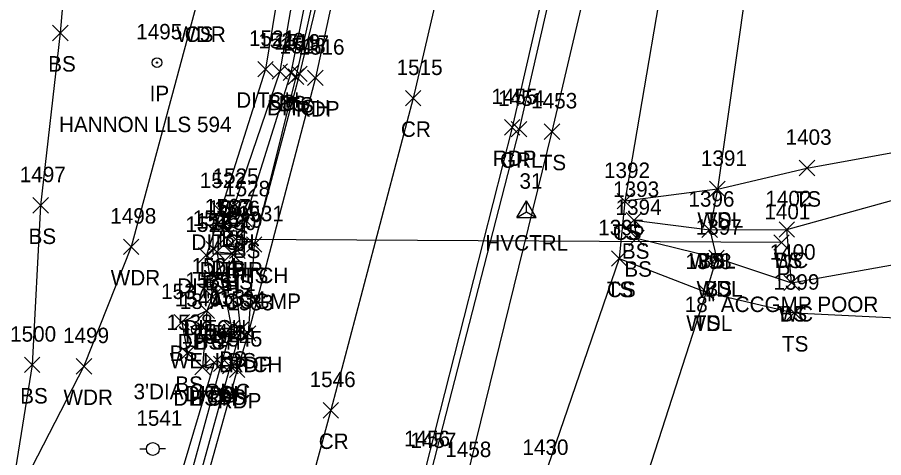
# Model space of a CAD drawing. Extents: x 1551995 to 1555700, y 777276 to 783130.
# Drawn here: x 1554796.1 to 1554908, y 777646.9 to 777703.8 of the extents above; entities that cross this region are included whole.
import ezdxf

# ---------------------------------------------------------------- set-up
doc = ezdxf.new("R2010")
doc.units = 0
for name, color, linetype in [('C_A', 7, 'Continuous'), ('C_I', 7, 'Continuous'), ('CPSM', 7, 'Continuous'), ('D_A', 7, 'Continuous'), ('D_C', 7, 'Continuous'), ('D_I', 7, 'Continuous'), ('D_TIC', 7, 'Continuous'), ('DCP', 7, 'Continuous'), ('DD', 7, 'Continuous'), ('DS', 7, 'Continuous'), ('L_A', 7, 'Continuous'), ('L_I', 7, 'Continuous'), ('L_TIC', 7, 'Continuous'), ('LAWA', 7, 'Continuous'), ('LAWE', 7, 'Continuous'), ('LELB', 7, 'Continuous'), ('M_A', 7, 'Continuous'), ('M_C', 7, 'Continuous'), ('M_I', 7, 'Continuous'), ('MPIR', 7, 'Continuous'), ('P_A', 7, 'Continuous'), ('P_I', 7, 'Continuous'), ('P_TIC', 7, 'Continuous'), ('PET', 7, 'Continuous'), ('PRC', 7, 'Continuous'), ('R_A', 7, 'Continuous'), ('R_I', 7, 'Continuous'), ('R_TIC', 7, 'Continuous'), ('RGR', 7, 'Continuous'), ('U_A', 7, 'Continuous'), ('U_C', 7, 'Continuous'), ('U_I', 7, 'Continuous'), ('UP', 7, 'Continuous'), ('UWW', 7, 'Continuous')]:
    doc.layers.add(name, color=color, linetype=linetype)

msp = doc.modelspace()

# ---------------------------------------------------------------- linework, layer by layer
at = {"layer": 'CPSM'}
for p, q in [((1554860.61, 777677.95), (1554861.86, 777680.12)), ((1554863.11, 777677.95), (1554861.86, 777680.12)), ((1554861.86, 777678.67), (1554861.86, 777680.12)), ((1554860.61, 777677.95), (1554861.86, 777678.67)), ((1554861.86, 777678.67), (1554861.86, 777678.67)), ((1554861.86, 777678.67), (1554863.11, 777677.95)), ((1554860.61, 777677.95), (1554863.11, 777677.95))]:
    msp.add_line(p, q, dxfattribs=at)
at = {"layer": 'D_TIC'}
for points in [[(1554827.13, 777696.14), (1554829.13, 777698.14)], [(1554829.13, 777696.14), (1554827.13, 777698.14)], [(1554831.08, 777695.16), (1554833.08, 777697.16)], [(1554833.08, 777695.16), (1554831.08, 777697.16)], [(1554821.33, 777677.76), (1554823.33, 777679.76)], [(1554823.33, 777677.76), (1554821.33, 777679.76)], [(1554822.04, 777674.36), (1554824.04, 777676.36)], [(1554824.04, 777674.36), (1554822.04, 777676.36)], [(1554823.28, 777674.12), (1554825.28, 777676.12)], [(1554825.28, 777674.12), (1554823.28, 777676.12)], [(1554825.68, 777673.46), (1554827.68, 777675.46)], [(1554827.68, 777673.46), (1554825.68, 777675.46)], [(1554893.81, 777673.72), (1554895.81, 777675.72)], [(1554895.81, 777673.72), (1554893.81, 777675.72)], [(1554819.5, 777672.08), (1554821.5, 777674.08)], [(1554821.5, 777672.08), (1554819.5, 777674.08)], [(1554820.28, 777666.69), (1554822.28, 777668.69)], [(1554822.28, 777666.69), (1554820.28, 777668.69)], [(1554819.54, 777664.87), (1554821.54, 777666.87)], [(1554821.54, 777664.87), (1554819.54, 777666.87)], [(1554824.9, 777661.94), (1554826.9, 777663.94)], [(1554826.9, 777661.94), (1554824.9, 777663.94)], [(1554818.99, 777657.61), (1554820.99, 777659.61)], [(1554820.99, 777657.61), (1554818.99, 777659.61)], [(1554820.52, 777658.17), (1554822.52, 777660.17)], [(1554822.52, 777658.17), (1554820.52, 777660.17)]]:
    msp.add_lwpolyline(points, dxfattribs=at)
at = {"layer": 'DCP'}
msp.add_lwpolyline([(1554894.81, 777674.72), (1554824.28, 777675.12)], dxfattribs=at)
at = {"layer": 'DD'}
for points in [[(1554922.06, 778109.96), (1554923.19, 778109.15), (1554925.69, 778108.05), (1554928.67, 778106.77), (1554922.03, 778089.94), (1554922.01, 778087.44), (1554918.96, 778075.67), (1554907.32, 778037.79), (1554897.01, 777996.11), (1554888.71, 777961.75), (1554879.52, 777917.82), (1554870.92, 777875.83), (1554859.53, 777827.03), (1554848.28, 777775.3), (1554842.42, 777742.65), (1554832.08, 777696.16), (1554826.68, 777674.46), (1554825.9, 777662.94)], [(1554853.39, 777826.98), (1554841.81, 777777.5), (1554835.76, 777743.69), (1554828.13, 777697.14), (1554822.33, 777678.76), (1554820.5, 777673.08), (1554821.28, 777667.69), (1554820.54, 777665.87), (1554819.99, 777658.61), (1554821.52, 777659.17), (1554812.27, 777628.19), (1554798.58, 777600.46), (1554777.91, 777552.75), (1554765.73, 777525.09), (1554749.72, 777489.17), (1554733.83, 777456.87), (1554735, 777456.04), (1554736.9, 777455.11), (1554739.85, 777453.59)]]:
    msp.add_lwpolyline(points, dxfattribs=at)
at = {"layer": 'DS'}
for p, q in [((1554821.38, 777677.21), (1554825.38, 777677.21)), ((1554821.38, 777673.21), (1554821.39, 777677.21)), ((1554822.38, 777676.21), (1554824.38, 777676.21)), ((1554822.38, 777674.21), (1554822.38, 777676.21)), ((1554824.38, 777676.21), (1554824.38, 777674.21)), ((1554825.38, 777677.21), (1554825.38, 777673.21)), ((1554823.38, 777675.22), (1554823.38, 777675.22)), ((1554824.38, 777674.21), (1554822.38, 777674.21)), ((1554825.38, 777673.21), (1554821.38, 777673.21)), ((1554823.88, 777673.21), (1554824.38, 777673.21))]:
    msp.add_line(p, q, dxfattribs=at)
at = {"layer": 'L_TIC'}
for points in [[(1554800.62, 777700.82), (1554802.62, 777702.82)], [(1554802.62, 777700.82), (1554800.62, 777702.82)], [(1554828.99, 777695.83), (1554830.99, 777697.83)], [(1554830.99, 777695.83), (1554828.99, 777697.83)], [(1554830.41, 777695.67), (1554832.41, 777697.67)], [(1554832.41, 777695.67), (1554830.41, 777697.67)], [(1554831.54, 777695.52), (1554833.54, 777697.52)], [(1554833.54, 777695.52), (1554831.54, 777697.52)], [(1554864.16, 777688.06), (1554866.16, 777690.06)], [(1554866.16, 777688.06), (1554864.16, 777690.06)], [(1554897.11, 777683.35), (1554899.11, 777685.35)], [(1554899.11, 777683.35), (1554897.11, 777685.35)], [(1554885.53, 777680.63), (1554887.53, 777682.63)], [(1554887.53, 777680.63), (1554885.53, 777682.63)], [(1554885.53, 777680.63), (1554887.53, 777682.63)], [(1554887.53, 777680.63), (1554885.53, 777682.63)], [(1554885.53, 777680.63), (1554887.53, 777682.63)], [(1554887.53, 777680.63), (1554885.53, 777682.63)], [(1554873.58, 777679.06), (1554875.58, 777681.06)], [(1554875.58, 777679.06), (1554873.58, 777681.06)], [(1554873.58, 777679.06), (1554875.58, 777681.06)], [(1554875.58, 777679.06), (1554873.58, 777681.06)], [(1554798.08, 777678.52), (1554800.08, 777680.52)], [(1554800.08, 777678.52), (1554798.08, 777680.52)], [(1554822.99, 777678.3), (1554824.99, 777680.3)], [(1554824.99, 777678.3), (1554822.99, 777680.3)], [(1554824.48, 777676.69), (1554826.48, 777678.69)], [(1554826.48, 777676.69), (1554824.48, 777678.69)], [(1554874.75, 777676.61), (1554876.75, 777678.61)], [(1554876.75, 777676.61), (1554874.75, 777678.61)], [(1554874.75, 777676.61), (1554876.75, 777678.61)], [(1554876.75, 777676.61), (1554874.75, 777678.61)], [(1554884.54, 777675.35), (1554886.54, 777677.35)], [(1554886.54, 777675.35), (1554884.54, 777677.35)], [(1554884.54, 777675.35), (1554886.54, 777677.35)], [(1554886.54, 777675.35), (1554884.54, 777677.35)], [(1554894.5, 777675.41), (1554896.5, 777677.41)], [(1554896.5, 777675.41), (1554894.5, 777677.41)], [(1554894.5, 777675.41), (1554896.5, 777677.41)], [(1554896.5, 777675.41), (1554894.5, 777677.41)], [(1554875.07, 777674.29), (1554877.07, 777676.29)], [(1554877.07, 777674.29), (1554875.07, 777676.29)], [(1554809.77, 777673.16), (1554811.77, 777675.16)], [(1554811.77, 777673.16), (1554809.77, 777675.16)], [(1554825.68, 777673.46), (1554827.68, 777675.46)], [(1554827.68, 777673.46), (1554825.68, 777675.46)], [(1554820.48, 777672.86), (1554822.48, 777674.86)], [(1554822.48, 777672.86), (1554820.48, 777674.86)], [(1554820.86, 777672.52), (1554822.86, 777674.52)], [(1554822.86, 777672.52), (1554820.86, 777674.52)], [(1554820.86, 777672.52), (1554822.86, 777674.52)], [(1554822.86, 777672.52), (1554820.86, 777674.52)], [(1554822.78, 777672.32), (1554824.78, 777674.32)], [(1554824.78, 777672.32), (1554822.78, 777674.32)], [(1554822.78, 777672.32), (1554824.78, 777674.32)], [(1554824.78, 777672.32), (1554822.78, 777674.32)], [(1554823.51, 777672.63), (1554825.51, 777674.63)], [(1554825.51, 777672.63), (1554823.51, 777674.63)], [(1554872.83, 777671.65), (1554874.83, 777673.65)], [(1554874.83, 777671.65), (1554872.83, 777673.65)], [(1554872.83, 777671.65), (1554874.83, 777673.65)], [(1554874.83, 777671.65), (1554872.83, 777673.65)], [(1554885.43, 777671.72), (1554887.43, 777673.72)], [(1554887.43, 777671.72), (1554885.43, 777673.72)], [(1554885.43, 777671.72), (1554887.43, 777673.72)], [(1554887.43, 777671.72), (1554885.43, 777673.72)], [(1554895.13, 777668.49), (1554897.13, 777670.49)], [(1554897.13, 777668.49), (1554895.13, 777670.49)], [(1554895.13, 777668.49), (1554897.13, 777670.49)], [(1554897.13, 777668.49), (1554895.13, 777670.49)], [(1554895.13, 777668.49), (1554897.13, 777670.49)], [(1554897.13, 777668.49), (1554895.13, 777670.49)], [(1554884.1, 777667.28), (1554886.1, 777669.28)], [(1554886.1, 777667.28), (1554884.1, 777669.28)], [(1554884.1, 777667.28), (1554886.1, 777669.28)], [(1554886.1, 777667.28), (1554884.1, 777669.28)], [(1554819.54, 777664.87), (1554821.54, 777666.87)], [(1554821.54, 777664.87), (1554819.54, 777666.87)], [(1554895.47, 777664.61), (1554897.47, 777666.61)], [(1554897.47, 777664.61), (1554895.47, 777666.61)], [(1554816.33, 777663.4), (1554818.33, 777665.4)], [(1554818.33, 777663.4), (1554816.33, 777665.4)], [(1554822.73, 777662.64), (1554824.73, 777664.64)], [(1554824.73, 777662.64), (1554822.73, 777664.64)], [(1554823.92, 777662.42), (1554825.92, 777664.42)], [(1554825.92, 777662.42), (1554823.92, 777664.42)], [(1554817.04, 777659.4), (1554819.04, 777661.4)], [(1554819.04, 777659.4), (1554817.04, 777661.4)], [(1554797, 777657.89), (1554799, 777659.89)], [(1554799, 777657.89), (1554797, 777659.89)], [(1554803.68, 777657.7), (1554805.68, 777659.7)], [(1554805.68, 777657.7), (1554803.68, 777659.7)], [(1554818.99, 777657.61), (1554820.99, 777659.61)], [(1554820.99, 777657.61), (1554818.99, 777659.61)], [(1554821.4, 777658.03), (1554823.4, 777660.03)], [(1554823.4, 777658.03), (1554821.4, 777660.03)], [(1554822.59, 777657.72), (1554824.59, 777659.72)], [(1554824.59, 777657.72), (1554822.59, 777659.72)]]:
    msp.add_lwpolyline(points, dxfattribs=at)
at = {"layer": 'LAWA'}
for points in [[(1554924.17, 777845.95), (1554911.99, 777797.39), (1554901.73, 777752.36), (1554891.43, 777715.92), (1554886.53, 777681.63), (1554885.54, 777676.35), (1554886.43, 777672.72), (1554885.1, 777668.28), (1554876.24, 777640.92), (1554874.65, 777639.02), (1554865.05, 777604.93), (1554832.26, 777556.58), (1554828.6, 777545), (1554825.77, 777534.55), (1554825.26, 777531.03), (1554824.11, 777527.47), (1554817.13, 777514.36), (1554810.78, 777500.84), (1554797.7, 777469.38), (1554813.54, 777462.7)], [(1554848.67, 777827.4), (1554836.72, 777779.63), (1554829.79, 777744.11), (1554825.78, 777741.3), (1554822.18, 777720.94), (1554819.26, 777705.66), (1554810.77, 777674.16), (1554804.68, 777658.7), (1554794.95, 777639.81), (1554796.98, 777635.44), (1554794.4, 777626.38), (1554790.25, 777608.46), (1554781.8, 777582.48), (1554770.39, 777556.32), (1554759.95, 777527.2), (1554742.53, 777489.58), (1554728.19, 777462.54)]]:
    msp.add_lwpolyline(points, dxfattribs=at)
at = {"layer": 'LAWE'}
for points in [[(1554896.13, 777669.49), (1554914.18, 777672.74), (1554933.67, 777664.23), (1554957.57, 777659.67), (1554982.43, 777660.34), (1555001.98, 777663.11), (1555028.12, 777669.98), (1555046.42, 777677.46), (1555063.93, 777692.17), (1555074.78, 777708.2), (1555088.15, 777717.7), (1555098.22, 777729.19), (1555108.92, 777737.75), (1555125.5, 777739.97), (1555133.42, 777752.91), (1555147.36, 777756.73)], [(1554896.13, 777669.49), (1554895.5, 777676.41), (1554916.66, 777682.24), (1554936.86, 777671.45), (1554957.7, 777666.95), (1554983.51, 777668.08)]]:
    msp.add_lwpolyline(points, dxfattribs=at)
at = {"layer": 'LELB'}
for points in [[(1554956.78, 778082.85), (1554952.54, 778067.25), (1554941.7, 778025.45), (1554932.23, 777987.42), (1554924.92, 777953.42), (1554914.28, 777909.64), (1554906.04, 777867.54), (1554895.88, 777821.34), (1554882.23, 777767.05), (1554874.85, 777730.37), (1554865.16, 777689.06), (1554854.06, 777643.96), (1554841.07, 777598.56), (1554825.8, 777560.58)], [(1554954.84, 778026.93), (1554940.94, 777981.64), (1554932.87, 777954.14), (1554929.76, 777924.84), (1554918.75, 777893.91), (1554912.39, 777848.48), (1554900.26, 777799.7), (1554891.71, 777757.62), (1554881.43, 777720.27), (1554874.58, 777680.06), (1554873.83, 777672.65), (1554864.12, 777644.24), (1554854.56, 777607.14), (1554832.26, 777556.58)], [(1554818.74, 777989.99), (1554826.95, 777965.67), (1554828.21, 777938.79), (1554827.61, 777892.43), (1554825.56, 777859.47), (1554820.31, 777829.58), (1554817.04, 777800.55), (1554813.37, 777784.98), (1554810.59, 777751.68), (1554805.09, 777735), (1554803.57, 777724.87), (1554801.62, 777701.82), (1554799.08, 777679.52), (1554798, 777658.89), (1554794.95, 777639.81), (1554778.13, 777607.5), (1554759.36, 777559.57), (1554752.31, 777545.79)], [(1554870.92, 777875.83), (1554861.08, 777826.54), (1554850.05, 777774.56), (1554843.76, 777742.91), (1554832.54, 777696.52), (1554826.68, 777674.46)], [(1554855.73, 777827.33), (1554843.83, 777776.52), (1554838.11, 777743.68), (1554829.99, 777696.83), (1554823.99, 777679.3), (1554821.48, 777673.86), (1554821.86, 777673.52), (1554823.73, 777663.64), (1554822.4, 777659.03), (1554813.94, 777627.98), (1554800.18, 777599.92), (1554780.06, 777551.51), (1554767.45, 777524.55), (1554751.73, 777488.16), (1554735, 777456.04)], [(1554857.76, 777827.38), (1554846.36, 777775.83), (1554840.77, 777743.18), (1554831.41, 777696.67), (1554825.48, 777677.69), (1554824.51, 777673.63), (1554823.78, 777673.32), (1554824.92, 777663.42), (1554823.59, 777658.72), (1554814.97, 777627.54), (1554801.99, 777599.47), (1554782.65, 777550.32), (1554769.22, 777523.47), (1554754.18, 777487.46), (1554736.9, 777455.11)], [(1554886.53, 777681.63), (1554898.11, 777684.35), (1554919.59, 777688.24), (1554946.32, 777678.67), (1554960.8, 777672.01), (1554976.86, 777671.82)], [(1554886.53, 777681.63), (1554874.58, 777680.06)], [(1554875.75, 777677.61), (1554876.07, 777675.29), (1554886.43, 777672.72), (1554896.13, 777669.49)], [(1554875.75, 777677.61), (1554885.54, 777676.35), (1554895.5, 777676.41)], [(1554821.86, 777673.52), (1554823.78, 777673.32)], [(1554873.83, 777672.65), (1554885.1, 777668.28), (1554896.47, 777665.61), (1554911.4, 777664.89), (1554930.69, 777655.48), (1554958.85, 777648.16), (1554982.59, 777653.45), (1554998.31, 777654.1)], [(1554820.54, 777665.87), (1554817.33, 777664.4), (1554818.04, 777660.4), (1554819.99, 777658.61)]]:
    msp.add_lwpolyline(points, dxfattribs=at)
at = {"layer": 'MPIR'}
for radius in [0.625, 0.0833]:
    msp.add_circle((1554814.12, 777697.99), radius, dxfattribs=at)
at = {"layer": 'P_TIC'}
for points in [[(1554833.58, 777695.01), (1554835.58, 777697.01)], [(1554835.58, 777695.01), (1554833.58, 777697.01)], [(1554846.21, 777692.38), (1554848.21, 777694.38)], [(1554848.21, 777692.38), (1554846.21, 777694.38)], [(1554859.02, 777688.61), (1554861.02, 777690.61)], [(1554861.02, 777688.61), (1554859.02, 777690.61)], [(1554824.9, 777661.94), (1554826.9, 777663.94)], [(1554826.9, 777661.94), (1554824.9, 777663.94)], [(1554823.47, 777657.25), (1554825.47, 777659.25)], [(1554825.47, 777657.25), (1554823.47, 777659.25)], [(1554835.59, 777652.01), (1554837.59, 777654.01)], [(1554837.59, 777652.01), (1554835.59, 777654.01)]]:
    msp.add_lwpolyline(points, dxfattribs=at)
at = {"layer": 'PET'}
for points in [[(1554862.74, 777826.66), (1554851.19, 777774.32), (1554844.64, 777742.45), (1554834.58, 777696.01), (1554825.9, 777662.94), (1554824.47, 777658.25), (1554815.91, 777627.5), (1554805.87, 777597.98), (1554786.84, 777548.46), (1554774.55, 777520.74), (1554758.12, 777485.1), (1554742.1, 777452.42), (1554722.77, 777413.11), (1554709.98, 777388.33), (1554692.97, 777354.45), (1554662.63, 777294.3)], [(1554889.9, 777822.39), (1554877.4, 777767.74), (1554869.61, 777731.46), (1554860.02, 777689.61), (1554848.79, 777645.37), (1554834.77, 777600.99), (1554821.88, 777564.77), (1554812, 777537.71), (1554799.6, 777509.17), (1554784.62, 777476.27), (1554767.28, 777440.72), (1554755.97, 777417.1), (1554737.76, 777381.53), (1554717.46, 777342.52), (1554685.83, 777281.18)]]:
    msp.add_lwpolyline(points, dxfattribs=at)
at = {"layer": 'PRC'}
msp.add_lwpolyline([(1554876.72, 777824.26), (1554864.6, 777770.35), (1554858.03, 777739.92), (1554847.21, 777693.38), (1554836.59, 777653.01), (1554828.61, 777623.61), (1554818.04, 777593.07), (1554799.63, 777543.85), (1554787.19, 777515.25), (1554771.79, 777480.71), (1554754.78, 777446.13), (1554727.16, 777390.73), (1554704.95, 777347.63), (1554675, 777287.76)], dxfattribs=at)
at = {"layer": 'R_TIC'}
for points in [[(1554859.9, 777688.38), (1554861.9, 777690.38)], [(1554861.9, 777688.38), (1554859.9, 777690.38)]]:
    msp.add_lwpolyline(points, dxfattribs=at)
at = {"layer": 'RGR'}
msp.add_lwpolyline([(1555039.56, 778268.3), (1555013.62, 778223), (1554996.63, 778189.88), (1554979.88, 778154.08), (1554968.24, 778124.65), (1554958.2, 778096.32), (1554950.97, 778072.94), (1554937.27, 778027.95), (1554927.65, 777988.1), (1554919.66, 777954.37), (1554909.72, 777910.11), (1554900.5, 777868.18), (1554890.69, 777822.54), (1554878.36, 777767.59), (1554870.52, 777731.32), (1554860.9, 777689.38), (1554849.55, 777645.14), (1554835.81, 777600.33), (1554822.79, 777564.15), (1554817.07, 777548.72), (1554816.7, 777536.06)], dxfattribs=at)
at = {"layer": 'UP'}
for p, q in [((1554811.92, 777648.01), (1554812.74, 777648.01)), ((1554813.58, 777648.01), (1554813.58, 777648.01)), ((1554815.24, 777648.01), (1554814.41, 777648.01)), ((1554814.41, 777648.01), (1554814.41, 777648.01)), ((1554815.24, 777648.01), (1554815.24, 777648.01))]:
    msp.add_line(p, q, dxfattribs=at)
msp.add_circle((1554813.58, 777648.01), 0.833, dxfattribs=at)
at = {"layer": 'UWW'}
for radius in [0.625, 0.0833]:
    msp.add_circle((1554819.19, 777663.44), radius, dxfattribs=at)

# ---------------------------------------------------------------- texts
at = {"layer": 'C_A'}
msp.add_text('HVCTRL', height=2, dxfattribs=at).set_placement((1554856.55, 777673.67))
at = {"layer": 'C_I'}
msp.add_text('31', height=2, dxfattribs=at).set_placement((1554860.96, 777681.67))
at = {"layer": 'D_A'}
for s, p in [('DITCH', (1554824.36, 777692.14)), ('DITCH', (1554828.32, 777691.16)), ('DITCH', (1554818.57, 777673.76)), ('DITHR', (1554819.63, 777670.19)), ('DIB', (1554821.14, 777670.36)), ('P', (1554823.66, 777670.12)), ('P', (1554894.19, 777669.72)), ('DITCH', (1554822.92, 777669.46)), ('DITCH', (1554816.73, 777668.08)), ('DITCH', (1554817.51, 777662.69)), ('DITCH', (1554816.78, 777660.87)), ('DITCH', (1554822.14, 777657.94)), ('DITCH', (1554817.75, 777654.17)), ('DITCH', (1554816.23, 777653.61))]:
    msp.add_text(s, height=2, dxfattribs=at).set_placement(p)
at = {"layer": 'D_C'}
for s, p in [('18"ACCGMP', (1554817.06, 777666.12)), ('18" ACCGMP POOR', (1554882.31, 777665.72))]:
    msp.add_text(s, height=2, dxfattribs=at).set_placement(p)
at = {"layer": 'D_I'}
for s, p in [('1521', (1554826, 777700.14)), ('1518', (1554829.96, 777699.16)), ('1522', (1554819.64, 777681.76)), ('1567', (1554820.3, 777678.36)), ('1532', (1554820.71, 777678.19)), ('1566', (1554821.48, 777678.12)), ('1531', (1554824.56, 777677.46)), ('1401', (1554892.6, 777677.72)), ('1523', (1554817.8, 777676.08)), ('1524', (1554818.58, 777670.69)), ('1536', (1554817.79, 777668.87)), ('1533', (1554823.21, 777665.94)), ('1542', (1554818.82, 777662.17)), ('1539', (1554817.29, 777661.61))]:
    msp.add_text(s, height=2, dxfattribs=at).set_placement(p)
at = {"layer": 'L_A'}
for s, p in [('WDR', (1554816.62, 777700.66)), ('CS', (1554817.7, 777700.66)), ('BS', (1554800.06, 777696.82)), ('BS', (1554828.43, 777691.83)), ('BS', (1554829.85, 777691.67)), ('TS', (1554830.95, 777691.52)), ('TS', (1554863.57, 777684.06)), ('TS', (1554896.52, 777679.35)), ('WDL', (1554883.94, 777676.63)), ('TS', (1554884.93, 777676.63)), ('TS', (1554884.93, 777676.63)), ('BS', (1554797.52, 777674.52)), ('BS', (1554822.43, 777674.3)), ('TS', (1554872.98, 777675.06)), ('CS', (1554873.02, 777675.06)), ('BS', (1554823.92, 777672.69)), ('BS', (1554874.19, 777672.61)), ('BS', (1554874.19, 777672.61)), ('WDL', (1554882.95, 777671.35)), ('BS', (1554883.98, 777671.35)), ('WC', (1554893.81, 777671.41)), ('BS', (1554893.94, 777671.41)), ('BS', (1554874.51, 777670.29)), ('WDR', (1554808.14, 777669.16)), ('BS', (1554819.92, 777668.86)), ('BS', (1554820.3, 777668.52)), ('BS', (1554820.3, 777668.52)), ('BS', (1554822.95, 777668.63)), ('TS', (1554825.09, 777669.46)), ('BS', (1554822.22, 777668.32)), ('BS', (1554822.22, 777668.32)), ('TS', (1554872.24, 777667.65)), ('CS', (1554872.27, 777667.65)), ('WDL', (1554883.85, 777667.72)), ('BS', (1554884.87, 777667.72)), ('WC', (1554894.44, 777664.49)), ('WC', (1554894.44, 777664.49)), ('BS', (1554894.57, 777664.49)), ('WDL', (1554882.52, 777663.28)), ('TS', (1554883.51, 777663.28)), ('BS', (1554818.98, 777660.87)), ('TS', (1554894.88, 777660.61)), ('BS', (1554815.77, 777659.4)), ('BS', (1554822.17, 777658.64)), ('BS', (1554823.36, 777658.42)), ('BS', (1554816.48, 777655.4)), ('BS', (1554820.85, 777654.03)), ('BS', (1554796.44, 777653.89)), ('WDR', (1554802.04, 777653.7)), ('BS', (1554818.43, 777653.61)), ('BS', (1554822.03, 777653.72))]:
    msp.add_text(s, height=2, dxfattribs=at).set_placement(p)
at = {"layer": 'L_I'}
for s, p in [('1520', (1554827.21, 777699.83)), ('1519', (1554829.27, 777699.67)), ('1517', (1554830.42, 777699.52)), ('1453', (1554862.47, 777692.06)), ('1403', (1554895.34, 777687.35)), ('1391', (1554884.4, 777684.63)), ('1391', (1554884.4, 777684.63)), ('1391', (1554884.4, 777684.63)), ('1392', (1554871.88, 777683.06)), ('1392', (1554871.88, 777683.06)), ('1497', (1554796.39, 777682.52)), ('1525', (1554821.3, 777682.3)), ('1528', (1554822.79, 777680.69)), ('1393', (1554873.06, 777680.61)), ('1393', (1554873.06, 777680.61)), ('1396', (1554882.79, 777679.35)), ('1396', (1554882.79, 777679.35)), ('1402', (1554892.73, 777679.41)), ('1402', (1554892.73, 777679.41)), ('1531', (1554824.56, 777677.46)), ('1394', (1554873.37, 777678.29)), ('1498', (1554808.08, 777677.16)), ('1526', (1554818.73, 777676.86)), ('1527', (1554819.17, 777676.52)), ('1527', (1554819.17, 777676.52)), ('1529', (1554821.81, 777676.63)), ('1530', (1554821, 777676.32)), ('1530', (1554821, 777676.32)), ('1395', (1554871.13, 777675.65)), ('1395', (1554871.13, 777675.65)), ('1397', (1554883.74, 777675.72)), ('1397', (1554883.74, 777675.72)), ('1400', (1554893.28, 777672.49)), ('1400', (1554893.28, 777672.49)), ('1400', (1554893.28, 777672.49)), ('1398', (1554882.41, 777671.28)), ('1398', (1554882.41, 777671.28)), ('1536', (1554817.79, 777668.87)), ('1399', (1554893.77, 777668.61)), ('1537', (1554814.64, 777667.4)), ('1535', (1554821.03, 777666.64)), ('1534', (1554822.23, 777666.42)), ('1538', (1554815.35, 777663.4)), ('1500', (1554795.14, 777661.89)), ('1543', (1554819.71, 777662.03)), ('1499', (1554801.98, 777661.7)), ('1539', (1554817.29, 777661.61)), ('1544', (1554820.9, 777661.72)), ('1430', (1554861.34, 777647.24)), ('1458', (1554851.37, 777646.96))]:
    msp.add_text(s, height=2, dxfattribs=at).set_placement(p)
at = {"layer": 'M_A'}
msp.add_text('IP', height=2, dxfattribs=at).set_placement((1554813.17, 777692.99))
at = {"layer": 'M_C'}
msp.add_text('HANNON LLS 594', height=2, dxfattribs=at).set_placement((1554801.45, 777688.99))
at = {"layer": 'M_I'}
msp.add_text('1495', height=2, dxfattribs=at).set_placement((1554811.43, 777700.99))
at = {"layer": 'P_A'}
for s, p in [('RDP', (1554832.07, 777691.01)), ('CR', (1554845.64, 777688.38)), ('RDP', (1554857.51, 777684.61)), ('RDP', (1554823.39, 777657.94)), ('RDP', (1554821.96, 777653.25)), ('CR', (1554835.02, 777648.01))]:
    msp.add_text(s, height=2, dxfattribs=at).set_placement(p)
at = {"layer": 'P_I'}
for s, p in [('1516', (1554832.4, 777699.01)), ('1515', (1554845.08, 777696.38)), ('1455', (1554857.33, 777692.61)), ('1533', (1554823.21, 777665.94)), ('1545', (1554821.78, 777661.25)), ('1546', (1554833.84, 777656.01)), ('1456', (1554846.04, 777648.37))]:
    msp.add_text(s, height=2, dxfattribs=at).set_placement(p)
at = {"layer": 'R_A'}
msp.add_text('GRL', height=2, dxfattribs=at).set_placement((1554858.44, 777684.38))
at = {"layer": 'R_I'}
for s, p in [('1454', (1554858.2, 777692.38)), ('1457', (1554846.86, 777648.14))]:
    msp.add_text(s, height=2, dxfattribs=at).set_placement(p)
at = {"layer": 'U_A'}
msp.add_text('WELL', height=2, dxfattribs=at).set_placement((1554815.76, 777658.44))
at = {"layer": 'U_C'}
msp.add_text("3'DIA CONC", height=2, dxfattribs=at).set_placement((1554811.09, 777654.44))
at = {"layer": 'U_I'}
for s, p in [('1540', (1554816.41, 777666.44)), ('1541', (1554811.45, 777651.01))]:
    msp.add_text(s, height=2, dxfattribs=at).set_placement(p)

doc.saveas('drawing.dxf')
